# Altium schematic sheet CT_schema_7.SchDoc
size 278 x 170 mm
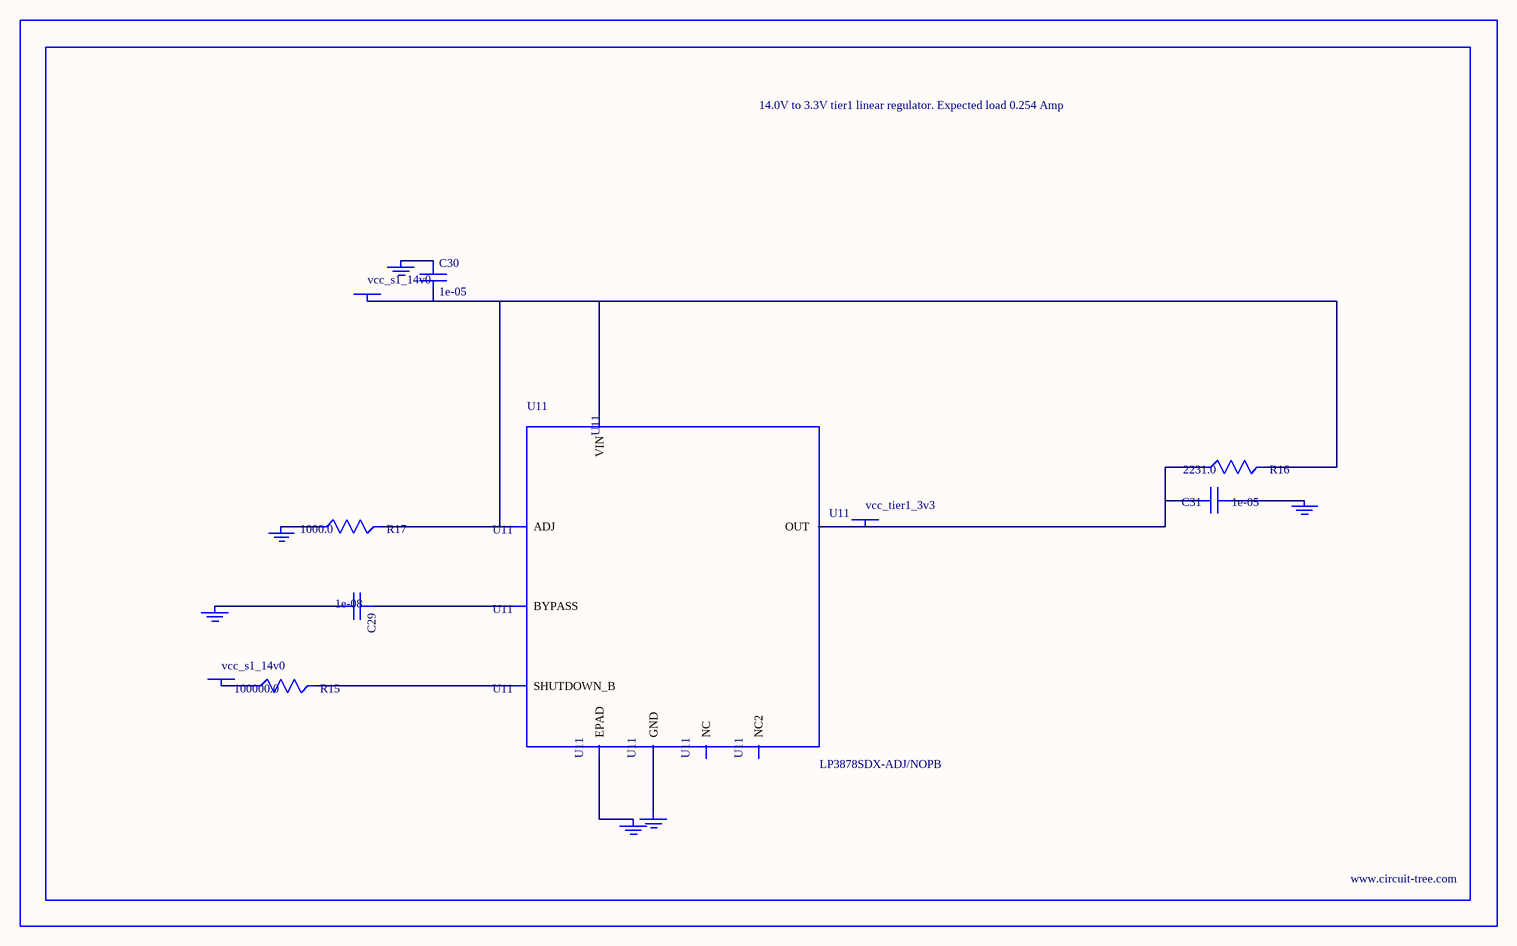
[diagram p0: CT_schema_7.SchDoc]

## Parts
BORDER6  (no value)
C29  1e-08  [C0402]
C30  1e-05  [C1210]
C31  1e-05  [C1210]
GND_INSTANCE_6_0  (no value)
GND_INSTANCE_6_1  (no value)
GND_INSTANCE_6_2  (no value)
GND_INSTANCE_6_3  (no value)
GND_INSTANCE_6_4  (no value)
GND_INSTANCE_6_5  (no value)
POWER_INSTANCE_6_0  vcc_s1_14v0
POWER_INSTANCE_6_1  vcc_s1_14v0
POWER_INSTANCE_6_2  vcc_tier1_3v3
R15  100000.0  [R0603]
R16  2231.0  [R0603]
R17  1000.0  [R0603]
U11  LP3878SDX-ADJ/NOPB  [WSON-8]

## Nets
NetC29_1: C29.1 U11.1(BYPASS)
NetC29_2: C29.2 GND_INSTANCE_6_0.0(GND)
NetC30_1: C30.1 GND_INSTANCE_6_1.0(GND)
NetC30_2: C30.2 POWER_INSTANCE_6_0.0(PWR) R16.2 R17.2 U11.4(VIN) U11.6(ADJ)
NetC31_1: C31.1 GND_INSTANCE_6_2.0(GND)
NetC31_2: C31.2 POWER_INSTANCE_6_2.0(PWR) R16.1 U11.5(OUT)
NetGND_INSTANCE_6_3_0: GND_INSTANCE_6_3.0(GND) R17.1
NetGND_INSTANCE_6_4_0: GND_INSTANCE_6_4.0(GND) U11.PAD(EPAD)
NetGND_INSTANCE_6_5_0: GND_INSTANCE_6_5.0(GND) U11.3(GND)
NetPOWER_INSTANCE_6_1_0: POWER_INSTANCE_6_1.0(PWR) R15.1
NetR15_2: R15.2 U11.8(SHUTDOWN_B)

Not connected (* = marked no-connect by the designer): U11 2(NC) 7(NC2)

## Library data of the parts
BORDER6 = BORDER_PAGE6
C29 = C0402C103K3RAC
C30 = C1210C106K5PACTU
C31 = GRM32DR61E106MA12L
GND_INSTANCE_6_0-GND_INSTANCE_6_5 = GND
POWER_INSTANCE_6_0-POWER_INSTANCE_6_2 = PWR
R15 = RC0603JR-07100KL
R16 = R16
R17 = RC0603JR-071KL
